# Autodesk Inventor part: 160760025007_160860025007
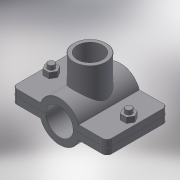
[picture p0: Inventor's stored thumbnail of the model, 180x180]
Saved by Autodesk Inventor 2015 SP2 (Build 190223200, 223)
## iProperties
Created: 2017-05
Part Number: 160760025007_160860025007
Material: Generic
Description: PLASSON SADDLE 25-3/4"
Document SubType Name: Modeling
Designer: KIM
Density: 1 g/cm^3
Appearance: Default
Author: KIM
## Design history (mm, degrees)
derived "16076.ipt"
feature "Solid1::16076.ipt"
feature "Solid2::16076.ipt"
tag "TaggingFeature1"
body "Solid1"
other parameters: "d0" = 37.5, "d1" = 75, "d2" = 12.5, "d3" = 25, "d5" = 0, "d6" = 3.75, "d7" = 75, "d8" = 0.1, "d10" = 0, "d11" = 0.25, "d14" = 31.3521, "d20" = 0.25, "d23" = 0.25, "d36" = 8, "d37" = 6.4, "d38" = 20.5, "d39" = 0, "d40" = 3, "d41" = 4, "d42" = 0, "d43" = 5, "d44" = 3, "d45" = 0, "d46" = 0.25, "d51" = 37, "d52" = 24.117, "d53" = 19, "d54" = 0, "d55" = 15, "d57" = 0, "d58" = 27, "d60" = 0, "d62" = 8, "d63" = 25, "d66" = 0, "d_" = 25, "B_" = 15, "G_" = 24.117, "A_" = 37, "L_" = 75, "l_2" = 19
